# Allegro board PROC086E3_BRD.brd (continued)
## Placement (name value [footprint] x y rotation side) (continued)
R402  360E_1%  [RES0402_0-5]  30.05 111.19 90 bottom
R403  7.5K  [RES0402_0-5]  34.35 110.57 180 bottom
R404  47K_1%  [RES0402_0-5]  14.22 109.3 270 bottom
R405  10K  [RES0402_0-5#2]  31.6 106.4 180 bottom
R406  47K_1%  [RES0402_0-5]  14.22 106.2 90 bottom
R407  10K  [RES0402_0-5#2]  31.6 105.23 0 bottom
R408  1.5K_1%  [RES0402_0-5#2]  31.11 103.59 90 bottom
R409  7.5K  [RES0402_0-5]  35.11 103.23 180 bottom
R410  3.74K_1%  [RES0402_0-5#2]  33.45 102.61 90 bottom
R411  360E_1%  [RES0402_0-5]  29.48 102.98 0 bottom
R412  47.5E_1%  [RES0402_0-5#2]  16.36 102.43 180 bottom
R413  360E_1%  [RES0402_0-5]  26.98 102.61 270 bottom
R414  4.75K_1%  [RES0402_0-5#2]  25.75 102.61 90 bottom
R415  7.5K  [RES0402_0-5]  35.11 102 180 bottom
R416  47E  [RES0402_0-5]  33.26 100.61 0 bottom
R417  1.5K  [RES0402_0-5#2]  34.96 99.95 90 bottom
R418  49.9E_1%  [RES0402_0-5#2]  21.48 96.41 0 bottom
R419  0E  [RES0402_0-5#2]  26.16 95.92 270 bottom
R420  0E  [RES0402_0-5#2]  25.09 95.92 270 bottom
R421  100K  [RES0402_0-5]  24 95.92 90 bottom
R422  1.5K  [RES0402_0-5#2]  37.65 95.68 90 bottom
R423  3K  [RES0402_0-5#2]  31.05 95.43 0 bottom
R424  150K_1%  [RES0402_0-5#2]  21.48 95.26 180 bottom
R425  5.9K_1%  [RES0402_0-5#2]  16.46 91.85 270 bottom
R426  1.5K  [RES0402_0-5#2]  35.68 91.53 270 bottom
R427  0E  [RES0402_0-5#2]  14.8 91.36 0 bottom
R428  47E  [RES0402_0-5]  33.91 90.93 0 bottom
R429  47E  [RES0402_0-5]  33.26 89.96 0 bottom
R430  0E  [RES0402_0-5#2]  14.8 89.38 0 bottom
R431  1.5K  [RES0402_0-5#2]  34.96 89.4 90 bottom
R432  5.9K_1%  [RES0402_0-5#2]  16.46 88.89 90 bottom
R433  150K_1%  [RES0402_0-5#2]  22.13 86.79 180 bottom
R434  0E  [RES0402_0-5#2]  60.13 89.34 270 bottom
R435  3K  [RES0402_0-5#2]  31.05 85.58 0 bottom
R436  0E  [RES0402_0-5#2]  26.16 85.09 90 bottom
R437  0E  [RES0402_0-5#2]  25.09 85.09 90 bottom
R438  100K  [RES0402_0-5]  24 85.09 270 bottom
R439  1.5K  [RES0402_0-5#2]  37.65 85.08 90 bottom
R440  49.9E_1%  [RES0402_0-5#2]  22.13 84.6 0 bottom
R441  1.5K  [RES0402_0-5#2]  18.82 70.63 270 bottom
R442  47E  [RES0402_0-5]  17.11 70 0 bottom
R443  1.5K  [RES0402_0-5#2]  35.68 80.83 270 bottom
R444  47E  [RES0402_0-5]  33.91 80.22 0 bottom
R445  1.5K  [RES0402_0-5#2]  20.82 74.95 90 bottom
R446  0E  [RES0402_0-5#2]  60.13 77.55 90 bottom
R447  47E  [RES0402_0-5]  16.46 79.9 0 bottom
R448  1.5K  [RES0402_0-5#2]  18.17 79.33 90 bottom
R449  3K  [RES0402_0-5#2]  14.12 75.55 0 bottom
R450  1.5K  [RES0402_0-5#2]  17.17 70 0 top
R451  47E  [RES0402_0-5]  18.88 70.63 270 top
R452  1.5K  [RES0402_0-5#2]  20.82 74.95 90 top
R453  47E  [RES0402_0-5]  33.26 67.53 0 bottom
R454  1.5K  [RES0402_0-5#2]  34.96 66.92 90 bottom
R455  47E  [RES0402_0-5]  19.43 79.33 90 top
R456  1.5K  [RES0402_0-5#2]  17.72 79.9 0 top
R457  3K  [RES0402_0-5#2]  16.03 79.41 90 top
R458  49.9E_1%  [RES0402_0-5#2]  21.48 63.22 0 bottom
R459  1.5K  [RES0402_0-5#2]  37.65 62.74 90 bottom
R460  0E  [RES0402_0-5#2]  26.26 62.73 270 bottom
R461  0E  [RES0402_0-5#2]  25.09 62.73 270 bottom
R462  100K  [RES0402_0-5]  24.05 62.73 90 bottom
R463  3K  [RES0402_0-5#2]  31.05 62.24 0 bottom
R464  150K_1%  [RES0402_0-5#2]  21.48 62.15 180 bottom
R465  5.9K_1%  [RES0402_0-5#2]  16.46 58.93 270 bottom
R466  1.5K  [RES0402_0-5#2]  35.68 58.52 270 bottom
R467  0E  [RES0402_0-5#2]  14.8 58.44 0 bottom
R468  47E  [RES0402_0-5]  33.91 57.95 0 bottom
R469  47E  [RES0402_0-5]  33.26 56.82 0 bottom
R470  0E  [RES0402_0-5#2]  14.8 56.46 0 bottom
R471  1.5K  [RES0402_0-5#2]  34.96 56.21 90 bottom
R472  5.9K_1%  [RES0402_0-5#2]  16.46 55.97 90 bottom
R473  0E  [RES0402_0-5#2]  82.06 54.28 0 bottom
R474  150K_1%  [RES0402_0-5#2]  22.13 53.7 180 bottom
R475  0E  [RES0402_0-5#2]  82.06 53.09 0 bottom
R476  3K  [RES0402_0-5#2]  31.05 52.39 0 bottom
R477  1.5K  [RES0402_0-5#2]  37.65 52.14 90 bottom
R478  0E  [RES0402_0-5#2]  26.26 51.9 90 bottom
R479  0E  [RES0402_0-5#2]  25.09 51.9 90 bottom
R480  100K  [RES0402_0-5]  24.05 51.9 270 bottom
R481  49.9E_1%  [RES0402_0-5#2]  22.13 51.41 0 bottom
R482  10K  [RES0402_0-5#2]  22.32 49.23 180 bottom
R483  360E_1%  [RES0402_0-5]  23.98 43.07 0 bottom
R484  5.6K_1%  [RES0402_0-5#2]  23.98 41.84 180 bottom
R485  10K  [RES0402_0-5#2]  96.08 48.27 0 bottom
R486  1K_1%  [RES0402_0-5#2]  82.25 48.24 180 bottom
R487  10K  [RES0402_0-5#2]  22.32 48.06 0 bottom
R488  47.5E_1%  [RES0402_0-5#2]  16.36 47.96 180 bottom
R489  1.5K  [RES0402_0-5#2]  35.68 47.92 270 bottom
R490  47E  [RES0402_0-5]  33.91 47.32 0 bottom
R491  10K  [RES0402_0-5#2]  96.08 47.13 0 bottom
R492  1.5K_1%  [RES0402_0-5#2]  22.32 46.89 180 bottom
R493  7.5K  [RES0402_0-5]  27.29 45.87 180 bottom
R494  1.5K_1%  [RES0402_0-5#2]  25.64 45.25 90 bottom
R495  360E_1%  [RES0402_0-5]  23 45.25 90 bottom
R496  7.5K  [RES0402_0-5]  27.3 44.63 180 bottom
R497  47K_1%  [RES0402_0-5]  14.22 44.18 270 bottom
R498  10K  [RES0402_0-5#2]  46.75 46.93 0 bottom
R499  10K  [RES0402_0-5#2]  22.38 40.77 180 bottom
R500  47K_1%  [RES0402_0-5]  14.22 41.09 90 bottom
R501  10K  [RES0402_0-5#2]  22.38 39.6 0 bottom
R502  1.5K_1%  [RES0402_0-5#2]  23.26 37.81 90 bottom
R503  7.5K  [RES0402_0-5]  27.3 37.44 180 bottom
R504  47.5E_1%  [RES0402_0-5#2]  16.36 37.32 180 bottom
R505  1.5K_1%  [RES0402_0-5#2]  25.64 36.83 90 bottom
R506  360E_1%  [RES0402_0-5]  21.4 37.19 0 bottom
R507  360E_1%  [RES0402_0-5]  19.93 36.83 270 bottom
R508  5.6K_1%  [RES0402_0-5#2]  18.7 36.83 90 bottom
R509  7.5K  [RES0402_0-5]  27.3 36.21 180 bottom
R510  10K  [RES0402_0-5#2]  22.32 32.89 180 bottom
R511  360E_1%  [RES0402_0-5]  23.98 26.75 0 bottom
R512  5.6K_1%  [RES0402_0-5#2]  23.98 25.52 180 bottom
R513  10K  [RES0402_0-5#2]  22.32 31.72 0 bottom
R514  47.5E_1%  [RES0402_0-5#2]  16.36 31.62 180 bottom
R515  1.5K_1%  [RES0402_0-5#2]  22.32 30.56 180 bottom
R516  7.5K  [RES0402_0-5]  27.29 29.53 180 bottom
R517  3.74K_1%  [RES0402_0-5#2]  25.64 28.92 270 bottom
R518  360E_1%  [RES0402_0-5]  23 28.92 90 bottom
R519  7.5K  [RES0402_0-5]  27.3 28.3 180 bottom
R520  47K_1%  [RES0402_0-5]  14.22 27.93 270 bottom
R521  10K  [RES0402_0-5#2]  23.76 24.26 180 bottom
R522  47K_1%  [RES0402_0-5]  14.22 24.68 90 bottom
R523  10K  [RES0402_0-5#2]  23.76 23.09 0 bottom
R524  1.5K_1%  [RES0402_0-5#2]  23.27 21.47 90 bottom
R525  7.5K  [RES0402_0-5]  27.3 21.11 180 bottom
R526  47.5E_1%  [RES0402_0-5#2]  16.36 20.98 180 bottom
R527  3.74K_1%  [RES0402_0-5#2]  25.64 20.49 90 bottom
R528  360E_1%  [RES0402_0-5]  21.59 20.89 0 bottom
R529  360E_1%  [RES0402_0-5]  19.93 20.49 270 bottom
R530  5.6K_1%  [RES0402_0-5#2]  18.7 20.49 90 bottom
R531  7.5K  [RES0402_0-5]  27.3 19.88 180 bottom
R532  22E_1%  [RES0402_0-5]  65.53 164.4 90 top
R533  22E_1%  [RES0402_0-5]  66.75 164.4 90 top
R534  0E  [RES0402_0-5]  28.99 186.77 180 bottom
R535  0E  [RES0402_0-5]  28.99 185.58 180 bottom
R536  0E  [RES0603_0-75]  88.95 117.94 180 bottom
R537  0E  [RES0603_0-75]  90.43 117.94 0 bottom
R538  0E  [RES0402_0-5]  66.79 70.46 180 bottom
R539  0E  [RES0402_0-5]  65.95 70.46 0 bottom
SW1  EG-1218  [SW3_98-42_460X160_TH]  29.08 139.39 90 bottom
TP1  -  [TP40_SMD]  68.76 113.83 270 bottom
TP2  -  [TP40_SMD]  68.4 111.35 0 bottom
TP3  -  [TP40_SMD]  68.4 105.78 0 bottom
TP4  5002  [TP_CIR67D40_TH_4-6]  35.51 173.85 90 bottom
TP5  THRU HOLE  [TP_40X65]  73 94.67 180 bottom
TP6  THRU HOLE  [TP_40X65]  98.22 94.53 180 bottom
TP7  THRU HOLE  [TP_40X65]  95.2 81.47 180 bottom
TP8  THRU HOLE  [TP_40X65]  94.77 75.16 180 bottom
TP9  -  [TP40_SMD]  65.92 68.29 90 bottom
TP10  -  [TP40_SMD]  95.14 52.13 0 top
TP11  -  [TP40_SMD]  95.27 49.88 0 top
TP12  THRU HOLE  [TP_40X65]  99.14 47.33 180 bottom
TP13  -  [TP40_SMD]  41.19 46.43 0 top
TP14  -  [TP40_SMD]  41.19 43.13 0 top
TP15  -  [TP40_SMD]  45.75 193.92 180 bottom
TP16  -  [TP40_SMD]  45.75 191.8 180 bottom
TP17  -  [TP40_SMD]  24.36 187.89 270 bottom
TP18  -  [TP40_SMD]  66.07 186.29 180 bottom
TP19  -  [TP40_SMD]  20.15 186.77 90 bottom
TP21  -  [TP40_SMD]  20.23 180.87 90 bottom
TP22  -  [TP40_SMD]  28.93 179.73 90 bottom
TP23  -  [TP40_SMD]  20.23 178.73 90 bottom
TP24  -  [TP40_SMD]  65.56 178.47 180 bottom
TP25  -  [TP40_SMD]  99.99 174.75 90 bottom
TP26  -  [TP40_SMD]  67.57 176.94 180 bottom
TP27  -  [TP40_SMD]  18.1 175.98 90 bottom
TP28  -  [TP40_SMD]  25.76 175.88 90 bottom
TP29  -  [TP40_SMD]  23.58 175.88 90 bottom
TP30  -  [TP40_SMD]  27.41 174.38 90 bottom
TP31  -  [TP40_SMD]  26.69 162.7 90 bottom
TP32  -  [TP40_SMD]  56.77 152.91 270 bottom
TP33  -  [TP40_SMD]  65.75 160.11 0 bottom
TP34  -  [TP40_SMD]  63.79 160.11 0 bottom
TP35  -  [TP20_SMD]  80.06 158.96 180 bottom
TP36  -  [TP20_SMD]  82.42 159.06 180 bottom
TP37  -  [TP20_SMD]  77.32 158.76 180 bottom
TP38  -  [TP40_SMD]  71.39 156.29 0 bottom
TP39  -  [TP40_SMD]  73.47 155.41 0 bottom
TP40  -  [TP20_SMD]  89.54 155.15 0 bottom
TP41  -  [TP40_SMD]  54.94 134.56 270 bottom
TP42  -  [TP40_SMD]  48.26 149.33 0 bottom
TP43  -  [TP40_SMD]  46.1 149.33 0 bottom
TP44  -  [TP40_SMD]  81.89 145.09 90 bottom
TP45  -  [TP40_SMD]  77.99 144.73 90 bottom
TP46  -  [TP40_SMD]  72.85 145.3 90 bottom
TP47  -  [TP40_SMD]  39.12 140.95 0 bottom
TP48  -  [TP40_SMD]  48.46 136.51 0 bottom
TP49  -  [TP40_SMD]  46.33 136.51 0 bottom
TP50  -  [TP40_SMD]  44.42 136.51 0 bottom
TP51  -  [TP40_SMD]  91.3 128.51 180 bottom
TP52  -  [TP40_SMD]  93.85 128.38 180 bottom
TP53  -  [TP40_SMD]  93.85 126.47 180 bottom
TP54  -  [TP40_SMD]  60.66 126.14 270 bottom
TP55  -  [TP40_SMD]  81.89 124.82 180 bottom
TP56  -  [TP40_SMD]  79.83 124.82 180 bottom
TP57  5002  [TP_CIR67D40_TH_4-6]  22.6 80.03 270 bottom
TP58  -  [TP20_SMD]  51.61 62.24 180 bottom
TP59  -  [TP20_SMD]  51.61 63.25 180 bottom
TP60  -  [TP20_SMD]  41.35 59.91 180 bottom
TP61  -  [TP20_SMD]  41.35 60.91 180 bottom
TP62  -  [TP20_SMD]  33.28 23.5 180 bottom
TP63  -  [TP20_SMD]  34.28 23.5 180 bottom
TP64  -  [TP20_SMD]  42.01 29.42 180 bottom
TP65  -  [TP20_SMD]  42.01 28.42 180 bottom
TP66  -  [TP20_SMD]  42.47 34.8 180 bottom
TP67  -  [TP20_SMD]  42.47 35.8 180 bottom
TP68  -  [TP20_SMD]  37.08 45.75 180 bottom
TP69  -  [TP20_SMD]  37.08 44.75 180 bottom
TP70  -  [TP20_SMD]  45.47 96.43 180 bottom
TP71  -  [TP20_SMD]  45.47 97.44 180 bottom
TP72  -  [TP20_SMD]  39.12 88.81 180 bottom
TP73  -  [TP20_SMD]  40.12 88.81 180 bottom
TP74  -  [TP20_SMD]  40.55 74.79 180 bottom
TP75  -  [TP20_SMD]  24.68 76.83 180 bottom
TP76  -  [TP20_SMD]  23.68 76.83 180 bottom
TP77  -  [TP20_SMD]  41.55 74.79 180 bottom
TP78  -  [TP20_SMD]  38.61 107.44 180 bottom
TP79  -  [TP20_SMD]  39.61 107.44 180 bottom
TP80  -  [TP20_SMD]  39.02 115.03 180 bottom
TP81  -  [TP20_SMD]  40.02 115.03 180 bottom
TP82  -  [TP20_SMD]  34.09 119.93 180 bottom
TP83  -  [TP20_SMD]  34.09 120.93 180 bottom
TP84  -  [TP20_SMD]  33.67 123.35 180 bottom
TP85  -  [TP20_SMD]  32.67 123.35 180 bottom
TP86  -  [TP20_SMD]  82.96 117.64 180 bottom
TP87  -  [TP20_SMD]  84.02 116.49 180 bottom
TP88  -  [TP20_SMD]  82.99 116.49 180 bottom
TP89  -  [TP20_SMD]  84.03 114.51 180 bottom
TP90  -  [TP20_SMD]  83.82 117.64 180 bottom
TP91  -  [TP20_SMD]  81.98 108.01 180 bottom
TP92  -  [TP20_SMD]  83.02 108.01 180 bottom
TP93  -  [TP20_SMD]  60.44 106.39 180 bottom
TP94  -  [TP20_SMD]  81.97 109.33 180 bottom
TP95  -  [TP20_SMD]  92.41 117.01 180 bottom
TP96  -  [TP20_SMD]  93.44 116.01 180 bottom
TP97  -  [TP20_SMD]  92.41 118.51 180 bottom
TP98  -  [TP20_SMD]  93.44 118.51 180 bottom
TP99  -  [TP20_SMD]  93.44 117.01 180 bottom
TP100  -  [TP20_SMD]  93.44 119.51 180 bottom
TP101  -  [TP20_SMD]  92.48 124.54 180 bottom
TP102  -  [TP20_SMD]  61.28 133.67 180 bottom
TP103  -  [TP20_SMD]  60.91 27.9 180 bottom
TP104  -  [TP20_SMD]  80.33 53.51 180 bottom
TP105  -  [TP20_SMD]  19.02 176.87 180 bottom
TP106  -  [TP20_SMD]  59.28 133.67 180 bottom
TP107  -  [TP20_SMD]  23.08 185.48 180 bottom
TP108  -  [TP20_SMD]  30.77 186.77 180 bottom
TP109  -  [TP20_SMD]  27.58 185.48 180 bottom
TP110  -  [TP20_SMD]  47.9 131.68 180 bottom
TP111  -  [TP20_SMD]  46.58 131.73 180 bottom
TP112  -  [TP20_SMD]  40.89 145.97 180 bottom
TP113  -  [TP20_SMD]  40.84 147.11 180 bottom
TP114  -  [TP20_SMD]  59.28 128.1 180 bottom
TP115  -  [TP20_SMD]  59.28 127.08 180 bottom
TP116  -  [TP20_SMD]  71.34 122.45 180 bottom
TP117  -  [TP20_SMD]  67.26 160.57 180 bottom
TP118  -  [TP20_SMD]  75.44 171.86 180 bottom
TP119  -  [TP20_SMD]  75.44 170.99 180 bottom
TP120  -  [TP20_SMD]  60.6 159.67 180 bottom
TP121  -  [TP20_SMD]  70.74 157.46 180 bottom
TP122  -  [TP20_SMD]  60.66 158.81 180 bottom
TP123  -  [TP20_SMD]  80.82 49.13 180 bottom
TP124  -  [TP20_SMD]  65.89 144.08 180 bottom
TP125  -  [TP20_SMD]  86.22 141.79 180 bottom
TP126  -  [TP20_SMD]  56.08 155.46 180 bottom
TP127  -  [TP20_SMD]  83.72 76.37 180 bottom
TP128  -  [TP20_SMD]  83.72 77.39 180 bottom
TP129  -  [TP20_SMD]  63.88 129.84 180 bottom
TP130  -  [TP20_SMD]  62.81 130.13 180 bottom
TP131  -  [TP20_SMD]  44.1 166.89 180 bottom
TP132  -  [TP20_SMD]  38.49 166.89 180 bottom
TP133  -  [TP20_SMD]  83.77 127.51 180 bottom
TP134  -  [TP20_SMD]  83.72 128.43 180 bottom
TP135  -  [TP20_SMD]  73.53 156.83 180 bottom
TP136  -  [TP20_SMD]  29.01 169.17 180 bottom
TP137  -  [TP20_SMD]  92.41 100.51 180 bottom
TP138  -  [TP20_SMD]  92.47 113.36 180 bottom
TP139  -  [TP20_SMD]  53.37 153.75 180 bottom
TP140  -  [TP20_SMD]  50.95 154.85 180 bottom
TP141  -  [TP20_SMD]  51.94 154.85 180 bottom
TP142  -  [TP20_SMD]  31.44 165.75 180 bottom
TP143  -  [TP20_SMD]  97.49 64.32 180 bottom
TP144  -  [TP20_SMD]  96.47 64.32 180 bottom
TP145  -  [TP20_SMD]  83 59.13 180 bottom
TP146  -  [TP20_SMD]  83 65.63 180 bottom
TP147  -  [TP20_SMD]  84.03 59.13 180 bottom
TP148  -  [TP20_SMD]  65.33 146.24 180 bottom
TP149  -  [TP20_SMD]  67.87 146.24 180 bottom
TP150  -  [TP20_SMD]  66.57 146.24 180 bottom
TP151  -  [TP20_SMD]  94.51 39.61 180 bottom
TP152  -  [TP20_SMD]  92.46 122.56 180 bottom
TP153  -  [TP20_SMD]  93.44 120.51 180 bottom
TP154  -  [TP20_SMD]  93.44 121.51 180 bottom
TP155  -  [TP20_SMD]  74.32 119.79 180 bottom
TP156  -  [TP20_SMD]  81.99 130.79 180 bottom
TP157  -  [TP20_SMD]  92.41 109.01 180 bottom
TP158  -  [TP20_SMD]  83 97.01 180 bottom
TP159  -  [TP20_SMD]  84.03 98.01 180 bottom
TP160  -  [TP20_SMD]  84.03 97.01 180 bottom
TP161  -  [TP40_SMD]  44.9 40.33 180 bottom
TP162  -  [TP40_SMD]  56.35 51.71 180 bottom
TP164  -  [TP40_SMD]  60.02 110.39 180 bottom
TP165  -  [TP40_SMD]  59.53 103.92 180 bottom
TP167  -  [TP40_SMD]  34.11 184.12 180 bottom
TP168  -  [TP40_SMD]  26.8 188.9 180 bottom
TP169  -  [TP40_SMD]  59.84 47.43 180 bottom
TP170  -  [TP40_SMD]  62.18 110.35 180 bottom
TP171  -  [TP40_SMD]  41.18 39.69 270 bottom
TP172  -  [TP40_SMD]  58.4 89.24 90 bottom
U1  TLV7103318DSET  [WSON6_19-68_60X60]  62.2 194.45 180 top
U2  DS90UB926QSQE  [WQFN60_19-68_360X360_0-8]  24.58 180.23 90 top
U3  SN74AVC4T245DGVR  [TVSOP16_15-74_150X180]  39.09 170.92 270 top
U4  SN74AVC4T245DGVR  [TVSOP16_15-74_150X180]  43.9 170.92 270 top
U5  SN74AVC4T245DGVR  [TVSOP16_15-74_150X180]  48.72 170.92 270 top
U6  SN74AVCB164245VR  [TVSOP48_15-74_390X180_1-2]  56.74 170.92 90 top
U7  SN74AVCB164245VR  [TVSOP48_15-74_390X180_1-2]  68.05 170.92 90 top
U8  DS90UB921TRHSTQ1  [QFN48_19-68_280X280_0-8_EP5-2]  30.19 161.45 270 top
U9  PCA9306DCT  [SSOP8_25-59_120X110]  44.49 157.79 90 top
U10  SN74CBT16214CDGGR  [TSSOP56_19-68_560X240_1-2]  61.96 144.43 90 top
U11  SN74CBT16214CDGGR  [TSSOP56_19-68_560X240_1-2]  77.53 144.41 90 top
U12  SN74CBT16214CDGGR  [TSSOP56_19-68_560X240_1-2]  92.97 144.41 90 top
U13  SN74LVC2G14  [SC70-6]  26.2 138.29 90 top
U14  SN74AVC8T245PWR  [TSSOP24_25-59_315X180_1-2]  51.74 130.98 90 top
U15  TCA6416ARTWR  [WQFN24_19-68_160X160]  60.03 130.88 270 top
U16  OPA2322AIDGKR  [VSSOP8_25-59_120X120_1-1]  19.32 124.24 90 top
U17  SN74CB3Q3257PWR  [TSSOP16_25-59_205X180]  67.79 118.53 270 top
U18  OPA2322AIDGKR  [VSSOP8_25-59_120X120_1-1]  26.37 108.5 90 top
U19  PCM3168APAP  [HTQFP64_19-68_400X400_1-2_EP7-3X7]  52.34 107.14 180 top
U20  OPA2322AIDGKR  [VSSOP8_25-59_120X120_1-1]  33.91 95.67 90 top
U21  SN74LVC2G125DCUR  [VSSOP8_19-68_85X95]  65.16 94.35 270 bottom
U22  OPA2322AIDGKR  [VSSOP8_25-59_120X120_1-1]  22.13 90.37 90 top
U23  OPA2322AIDGKR  [VSSOP8_25-59_120X120_1-1]  33.91 85.06 90 top
U24  OPA2322AIDGKR  [VSSOP8_25-59_120X120_1-1]  28.98 72.55 270 top
U25  SN74LVC2G125DCUR  [VSSOP8_19-68_85X95]  63.58 69.84 270 bottom
U26  OPA2322AIDGKR  [VSSOP8_25-59_120X120_1-1]  28.98 72.55 270 bottom
U27  OPA2322AIDGKR  [VSSOP8_25-59_120X120_1-1]  33.91 62.74 90 top
U28  OPA2322AIDGKR  [VSSOP8_25-59_120X120_1-1]  22.13 57.45 90 top
U29  OPA2322AIDGKR  [VSSOP8_25-59_120X120_1-1]  33.91 52.14 90 top
U30  CAT24C256WI-GT3  [SOIC8_1-8]  74.35 51.01 180 top
U31  OPA2322AIDGKR  [VSSOP8_25-59_120X120_1-1]  19.32 42.56 90 top
U32  PCM3168APAP  [HTQFP64_19-68_400X400_1-2_EP7-3X7]  52.34 44.68 0 top
U33  OPA2322AIDGKR  [VSSOP8_25-59_120X120_1-1]  19.32 26.23 90 top
U34  TPD12S016PWR  [TSSOP24_25-59_315X180_1-2]  93.78 183.09 90 bottom
U35  SN74LVC2G125DCUR  [VSSOP8_19-68_85X95]  37 182.99 90 bottom
U36  PCA9306DCT  [SSOP8_25-59_120X110]  46.8 182.58 270 bottom
U37  PCA9306DCT  [SSOP8_25-59_120X110]  79.26 180.2 90 bottom
U38  24.000MHz  [OSC4_ASDMB_100X85_SMD_0-9]  38.52 179 180 bottom
U39  SN74LVC1G04DCKR  [SC70-5]  62.28 170.95 0 bottom
U40  TPS1H100AQPWPRQ1  [HTSSOP14_TPS1H100-Q1_180X200_1-2]  17.92 170.23 0 bottom
U41  TFP410PAP  [HTQFP64_19-68_400X400_1-2]  89.79 163.12 0 bottom
U42  CDCE813-Q1  [TSSOP14_25-59_205X180_1-2]  39.82 157.29 270 bottom
U43  TCA6416ARTWR  [WQFN24_19-68_160X160]  67 156.16 0 bottom
U44  TPS1H100AQPWPRQ1  [HTSSOP14_TPS1H100-Q1_180X200_1-2]  17.45 151.33 0 bottom
U45  DIR9001PW  [TSSOP28_25-59_390X180_1-2]  47.32 142.87 180 bottom
U46  OPA2322AIDGKR  [VSSOP8_25-59_120X120_1-1]  19.32 124.24 270 bottom
U47  OPA2322AIDGKR  [VSSOP8_25-59_120X120_1-1]  26.37 108.5 270 bottom
U48  OPA2322AIDGKR  [VSSOP8_25-59_120X120_1-1]  33.91 95.68 270 bottom
U49  OPA2322AIDGKR  [VSSOP8_25-59_120X120_1-1]  22.13 90.37 270 bottom
U50  OPA2322AIDGKR  [VSSOP8_25-59_120X120_1-1]  33.91 85.08 270 bottom
U51  OPA2322AIDGKR  [VSSOP8_25-59_120X120_1-1]  17.11 74.95 270 bottom
U52  OPA2322AIDGKR  [VSSOP8_25-59_120X120_1-1]  17.11 74.95 270 top
U53  OPA2322AIDGKR  [VSSOP8_25-59_120X120_1-1]  33.91 62.76 270 bottom
U54  OPA2322AIDGKR  [VSSOP8_25-59_120X120_1-1]  22.13 57.45 270 bottom
U55  OPA2322AIDGKR  [VSSOP8_25-59_120X120_1-1]  33.91 52.15 270 bottom
U56  OPA2322AIDGKR  [VSSOP8_25-59_120X120_1-1]  19.32 42.56 270 bottom
U57  OPA2322AIDGKR  [VSSOP8_25-59_120X120_1-1]  19.32 26.23 270 bottom
U179  OPA2322AIDGKR  [VSSOP8_25-59_120X120_1-1]  40.47 44.28 270 bottom
U180  OPA2322AIDGKR  [VSSOP8_25-59_120X120_1-1]  57.66 93.6 270 bottom
Y1  24.576MHz  [XTAL_CSM-7X_450X190_SMD_4-3]  58.98 143 90 bottom

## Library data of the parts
C1-C49 C51 C53-C63 C65-C71 C73-C88 C90-C121 C123-C133 C135-C167 C169-C182 C184-C195 C197-C203 C205-C278 C280-C285 C287-C292 C294-C300 C302-C331 C333-C337 C339-C358 C360-C365 C367-C372 C374-C379 C381-C385 C765-C774 = CAP
C50 C52 C64 C72 C89 C122 C134 C168 C183 C196 C204 C279 C286 C293 C301 C332 C338 C359 C366 C373 C380 = CAP_POL
D1-D4 = DIODE_TVS
FL1 FL2 FL4 FL6-FL15 FL20-FL25 = EMIFILTER_IND
FL3 FL5 FL16-FL19 = EMIFILTER_ACM
J1 J2 = CON_INT_60X2_M
J3 = RECP_16X2
J4 = CON_HDMI_19X1_TI
J5 J7 = CON_JACK4_EXG.0B.304
J6 = CON_FLEX_36X1_52559-3652
J8 J9 = CON_RCAJACK3_RCJ-02X
J10 = HEADER_8X1
J11-J13 J15 J16 J18 J19 = CON_AUDIOJACK6_STX-4235-3/3
J14 J20 = CON_PMC_20X2_F
J17 = CON_PMC_60X2_F_QSH-060
L1 = INDUCTOR
LD1-LD3 = LED_598-8170-107F
MOD1 = MODULE_PLR135T10
Q1-Q3 = MOSFET_2N7002_SOT23
R1-R8 R10 R11 R13-R25 R27-R30 R32 R47-R56 R58 R59 R62-R66 R68-R71 R96-R153 R155 R156 R158-R160 R162-R232 R234 R236-R269 R271-R273 R275 R277-R311 R313-R323 R325-R531 R534-R539 = RESISTOR
R26 R57 R60 R61 R67 R72-R95 R233 R235 = RESISTOR: signal model: RESISTOR_RES0402_0-5_0E_0E
R31 R33-R46 R154 R157 R161 R270 R274 R276 R312 R324 R532 R533 = RESISTOR: signal model: RESISTOR_RES0402_22E_1%_22E_1%
SW1 = SW3_SLIDE_EG1218
TP1-TP19 TP21-TP162 TP164 TP165 TP167-TP172 = TESTPOINT
U1 = TLV7103318D_WSON6
U2 = DS90UB926QSQ_WQFN60_TI
U3-U5 = SN74AVC4T245DGVR_TVSOP16
U6 U7 = SN74AVCB164245VR_TVSOP48
U8 = DS90UB921TRHSTQ1_WQFN48_TI
U9 U36 U37 = PCA9306DCT_SSOP8
U10-U12 = SN74CBT16214CDGGR_TSSOP56_TI
U13 = SN74LVC2G14DCKR_SC-70
U14 = SN74AVC8T245PWR_TSSOP24
U15 U43 = TCA6416ARTWR_WQFN24
U16 U18 U20 U22-U24 U26-U29 U31 U33 U46-U57 U179 U180 = OPA2350UA_SOIC8
U17 = SN74CB3Q3257PWR_TSSOP16
U19 U32 = PCM3168APAP_HTQFP64_TI
U21 U25 U35 = SN74LVC2G125DCUT_VSSOP8
U30 = CAT24C256WI-GT3_SOIC8
U34 = TPD12S016PW_TSSOP24
U38 = OSC4_ASDMB
U39 = SN74LVC1G04DCKR_SC70-5
U40 U44 = TPS1H100A-Q1_HTSSOP14
U41 = TFP410PAP_HTQFP64_TI
U42 = CDCE813QPWRQ1_TSSOP14
U45 = DIR9001PW_TSSOP28_TI
Y1 = CRY

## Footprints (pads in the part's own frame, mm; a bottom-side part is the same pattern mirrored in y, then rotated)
CAP0402_0-5
  rect 0.559x0.635 smd: 1(-0.49,0) 2(0.49,0)
CAP0402_0-75
  rect 0.559x0.635 smd: 1(-0.49,0) 2(0.49,0)
CAP0603_1
  rect 0.94x1.016 smd: 1(-0.8,0) 2(0.8,0)
CAP0805_1-5
  rect 1.143x1.448 smd: 1(-0.9,0) 2(0.9,0)
CAP1206_2
  rect 0.991x1.702 smd: 1(-1.35,0) 2(1.35,0)
CAP1206_2#2
  rect 1.143x1.803 smd: 1(-1.5,0) 2(1.5,0)
CAP_196-85_280X100_TH_6-5
  rect 1.448x1.448 hole 0.762: 1(0,0)
  round 1.448 hole 0.762: 2(5,0)
CAP_393-7_510X180_TH_10-5
  rect 1.549x1.549 hole 0.864: 1(0,0)
  round 1.549 hole 0.864: 2(10,0)
CAPCT0805H_1
  rect 0.66x1.549 smd: 1(-1.15,0) 2(1.15,0)
CON_19X1_10029449-001RLF_S_R_S_6-3
  rect 0.33x1.956 smd: 1(4.75,4.928) 2(4.25,4.928) 3(3.75,4.928) 4(3.25,4.928) 5(2.75,4.928) 6(2.25,4.928) 7(1.75,4.928) 8(1.25,4.928) 9(0.75,4.928) 10(0.25,4.928) 11(-0.25,4.928) 12(-0.75,4.928) 13(-1.25,4.928) 14(-1.75,4.928) 15(-2.25,4.928) 16(-2.75,4.928) 17(-3.25,4.928) 18(-3.75,4.928) 19(-4.25,4.928)
  round 2.007 hole 1.321: 20(7.25,3.928) 21(-7.25,3.928) 22(7.85,-0.972) 23(-7.85,-0.972)
CON_AV6_STX-4235-3-3_S_R_T_26
  oval 1.854x3.886 hole 1.981x4.013 unplated: (-7,0) (-3,0)
  rect 2.21x2.21 hole 1.524: 1A(0,0)
  round 2.21 hole 1.524: 1B(-10,0) 2A(1.25,7.5) 2B(-10,5) 5A(-11.25,7.5) 5B(0,5)
CON_FLEX1X36_52559-36_S_S_S_5-3
  rect 0.61x1.499 smd: 1(-8.75,-1.4) 2(-8.25,1.4) 3(-7.75,-1.4) 4(-7.25,1.4) 5(-6.75,-1.4) 6(-6.25,1.4) 7(-5.75,-1.4) 8(-5.25,1.4) 9(-4.75,-1.4) 10(-4.25,1.4) 11(-3.75,-1.4) 12(-3.25,1.4) 13(-2.75,-1.4) 14(-2.25,1.4) 15(-1.75,-1.4) 16(-1.25,1.4) 17(-0.75,-1.4) 18(-0.25,1.4) 19(0.25,-1.4) 20(0.75,1.4) 21(1.25,-1.4) 22(1.75,1.4) 23(2.25,-1.4) 24(2.75,1.4) 25(3.25,-1.4) 26(3.75,1.4) 27(4.25,-1.4) 28(4.75,1.4) 29(5.25,-1.4) 30(5.75,1.4) 31(6.25,-1.4) 32(6.75,1.4) 33(7.25,-1.4) 34(7.75,1.4) 35(8.25,-1.4) 36(8.75,1.4)
  rect 0.787x1.499 smd: SH1(-9.75,-1.4) SH2(-9.75,1.4) SH3(9.75,-1.4) SH4(9.75,1.4)
CON_JACK4_D4S20G-400A5_P_R_T_10-6
  rect 1.702x1.702 hole 1.016: 1(0,0)
  round 1.702 hole 1.016: 2(0,-2) 3(2,-2) 4(2,0)
  round 2.362 hole 1.676: SH1(-3.5,3.5) SH2(-3.5,-5.5) SH3(5.5,-5.5) SH4(5.5,3.5)
CON_PMC2X20_QSE-020-01-D-A_S_S_S_3-4
  round 0.889 hole 1.016 unplated: (-10.065,2.67) (10.065,2.67)
  rect 0.406x2.261 smd: 1(-7.595,-2.86) 2(-7.595,2.87) 3(-6.795,-2.86) 4(-6.795,2.87) 5(-5.995,-2.86) 6(-5.995,2.87) 7(-5.195,-2.86) 8(-5.195,2.87) 9(-4.395,-2.86) 10(-4.395,2.87) 11(-3.595,-2.86) 12(-3.595,2.87) 13(-2.795,-2.86) 14(-2.795,2.87) 15(-1.995,-2.86) 16(-1.995,2.87) 17(-1.195,-2.86) 18(-1.195,2.87) 19(-0.395,-2.86) 20(-0.395,2.87) 21(0.405,-2.86) 22(0.405,2.87) 23(1.205,-2.86) 24(1.205,2.87) 25(2.005,-2.86) 26(2.005,2.87) 27(2.805,-2.86) 28(2.805,2.87) 29(3.605,-2.86) 30(3.605,2.87) 31(4.405,-2.86) 32(4.405,2.87) 33(5.205,-2.86) 34(5.205,2.87) 35(6.005,-2.86) 36(6.005,2.87) 37(6.805,-2.86) 38(6.805,2.87) 39(7.605,-2.86) 40(7.605,2.87)
  rect 2.794x0.432 smd: 41(-8.065,0) 44(8.065,0)
  rect 4.699x0.432 smd: 42(-3.175,0) 43(3.175,0)
CON_PMC2X60_QSE-060-01-D-A_S_S_S_3-4
  round 0.889 hole 1.016 unplated: (-30.065,2.67) (30.065,2.67)
  rect 0.406x2.261 smd: 1(-27.595,-2.86) 2(-27.595,2.87) 3(-26.795,-2.86) 4(-26.795,2.87) 5(-25.995,-2.86) 6(-25.995,2.87) 7(-25.195,-2.86) 8(-25.195,2.87) 9(-24.395,-2.86) 10(-24.395,2.87) 11(-23.595,-2.86) 12(-23.595,2.87) 13(-22.795,-2.86) 14(-22.795,2.87) 15(-21.995,-2.86) 16(-21.995,2.87) 17(-21.195,-2.86) 18(-21.195,2.87) 19(-20.395,-2.86) 20(-20.395,2.87) 21(-19.595,-2.86) 22(-19.595,2.87) 23(-18.795,-2.86) 24(-18.795,2.87) 25(-17.995,-2.86) 26(-17.995,2.87) 27(-17.195,-2.86) 28(-17.195,2.87) 29(-16.395,-2.86) 30(-16.395,2.87) 31(-15.595,-2.86) 32(-15.595,2.87) 33(-14.795,-2.86) 34(-14.795,2.87) 35(-13.995,-2.86) 36(-13.995,2.87) 37(-13.195,-2.86) 38(-13.195,2.87) 39(-12.395,-2.86) 40(-12.395,2.87) 41(-7.595,-2.86) 42(-7.595,2.87) 43(-6.795,-2.86) 44(-6.795,2.87) 45(-5.995,-2.86) 46(-5.995,2.87) 47(-5.195,-2.86) 48(-5.195,2.87) 49(-4.395,-2.86) 50(-4.395,2.87) 51(-3.595,-2.86) 52(-3.595,2.87) 53(-2.795,-2.86) 54(-2.795,2.87) 55(-1.995,-2.86) 56(-1.995,2.87) 57(-1.195,-2.86) 58(-1.195,2.87) 59(-0.395,-2.86) 60(-0.395,2.87) 61(0.405,-2.86) 62(0.405,2.87) 63(1.205,-2.86) 64(1.205,2.87) 65(2.005,-2.86) 66(2.005,2.87) 67(2.805,-2.86) 68(2.805,2.87) 69(3.605,-2.86) 70(3.605,2.87) 71(4.405,-2.86) 72(4.405,2.87) 73(5.205,-2.86) 74(5.205,2.87) 75(6.005,-2.86) 76(6.005,2.87) 77(6.805,-2.86) 78(6.805,2.87) 79(7.605,-2.86) 80(7.605,2.87) 81(12.405,-2.86) 82(12.405,2.87) 83(13.205,-2.86) 84(13.205,2.87) 85(14.005,-2.86) 86(14.005,2.87) 87(14.805,-2.86) 88(14.805,2.87) 89(15.605,-2.86) 90(15.605,2.87) 91(16.405,-2.86) 92(16.405,2.87) 93(17.205,-2.86) 94(17.205,2.87) 95(18.005,-2.86) 96(18.005,2.87) 97(18.805,-2.86) 98(18.805,2.87) 99(19.605,-2.86) 100(19.605,2.87) 101(20.405,-2.86) 102(20.405,2.87) 103(21.205,-2.86) 104(21.205,2.87) 105(22.005,-2.86) 106(22.005,2.87) 107(22.805,-2.86) 108(22.805,2.87) 109(23.605,-2.86) 110(23.605,2.87) 111(24.405,-2.86) 112(24.405,2.87) 113(25.205,-2.86) 114(25.205,2.87) 115(26.005,-2.86) 116(26.005,2.87) 117(26.805,-2.86) 118(26.805,2.87) 119(27.605,-2.86) 120(27.605,2.87)
  rect 2.794x0.432 smd: 121(-28.065,0) 124(-11.935,0) 125(-8.065,0) 128(8.065,0) 129(11.935,0) 132(28.065,0)
  rect 4.699x0.432 smd: 122(-23.175,0) 123(-16.825,0) 126(-3.175,0) 127(3.175,0) 130(16.825,0) 131(23.175,0)
CON_PMC2X60_QTH-60-1-D-A_P_S_S_4-4
  round 0.889 hole 1.016 unplated: (-19.24,2.03) (19.239,2.03)
  rect 0.305x1.448 smd: 1(-17.251,3.08) 2(-17.251,-3.086) 3(-16.751,3.08) 4(-16.751,-3.086) 5(-16.251,3.08) 6(-16.251,-3.086) 7(-15.751,3.08) 8(-15.751,-3.086) 9(-15.251,3.08) 10(-15.251,-3.086) 11(-14.751,3.08) 12(-14.751,-3.086) 13(-14.251,3.08) 14(-14.251,-3.086) 15(-13.751,3.08) 16(-13.751,-3.086) 17(-13.251,3.08) 18(-13.251,-3.086) 19(-12.751,3.08) 20(-12.751,-3.086) 21(-12.251,3.08) 22(-12.251,-3.086) 23(-11.751,3.08) 24(-11.751,-3.086) 25(-11.251,3.08) 26(-11.251,-3.086) 27(-10.751,3.08) 28(-10.751,-3.086) 29(-10.251,3.08) 30(-10.251,-3.086) 31(-9.751,3.08) 32(-9.751,-3.086) 33(-9.251,3.08) 34(-9.251,-3.086) 35(-8.751,3.08) 36(-8.751,-3.086) 37(-8.251,3.08) 38(-8.251,-3.086) 39(-7.751,3.08) 40(-7.751,-3.086) 41(-7.251,3.08) 42(-7.251,-3.086) 43(-6.751,3.08) 44(-6.751,-3.086) 45(-6.251,3.08) 46(-6.251,-3.086) 47(-5.751,3.08) 48(-5.751,-3.086) 49(-5.251,3.08) 50(-5.251,-3.086) 51(-4.751,3.08) 52(-4.751,-3.086) 53(-4.251,3.08) 54(-4.251,-3.086) 55(-3.751,3.08) 56(-3.751,-3.086) 57(-3.251,3.08) 58(-3.251,-3.086) 59(-2.751,3.08) 60(-2.751,-3.086) 61(2.751,3.08) 62(2.751,-3.086) 63(3.251,3.08) 64(3.251,-3.086) 65(3.751,3.08) 66(3.751,-3.086) 67(4.251,3.08) 68(4.251,-3.086) 69(4.751,3.08) 70(4.751,-3.086) 71(5.251,3.08) 72(5.251,-3.086) 73(5.751,3.08) 74(5.751,-3.086) 75(6.251,3.08) 76(6.251,-3.086) 77(6.751,3.08) 78(6.751,-3.086) 79(7.251,3.08) 80(7.251,-3.086) 81(7.751,3.08) 82(7.751,-3.086) 83(8.251,3.08) 84(8.251,-3.086) 85(8.751,3.08) 86(8.751,-3.086) 87(9.251,3.08) 88(9.251,-3.086) 89(9.751,3.08) 90(9.751,-3.086) 91(10.251,3.08) 92(10.251,-3.086) 93(10.751,3.08) 94(10.751,-3.086) 95(11.251,3.08) 96(11.251,-3.086) 97(11.751,3.08) 98(11.751,-3.086) 99(12.251,3.08) 100(12.251,-3.086) 101(12.751,3.08) 102(12.751,-3.086) 103(13.251,3.08) 104(13.251,-3.086) 105(13.751,3.08) 106(13.751,-3.086) 107(14.251,3.08) 108(14.251,-3.086) 109(14.751,3.08) 110(14.751,-3.086) 111(15.251,3.08) 112(15.251,-3.086) 113(15.751,3.08) 114(15.751,-3.086) 115(16.251,3.08) 116(16.251,-3.086) 117(16.751,3.08) 118(16.751,-3.086) 119(17.251,3.08) 120(17.251,-3.086)
  rect 2.54x0.635 smd: 121(-18.441,0) 124(-1.551,0) 125(1.561,0) 128(18.451,0)
  rect 4.699x0.635 smd: 122(-13.172,0) 123(-6.822,0) 126(6.832,0) 127(13.182,0)
CON_RCAJACK3_RCJ-02X_S_S_T_16
  rect 2.692x2.692 hole 1.981: 1(0,0)
  round 2.362 hole 1.676: 2(5.15,1.6)
  round 2.692 hole 1.981: 3(10.3,0)
DIO_SMC
  rect 2.21x3.099 smd: 1(-3.5,0) 2(3.5,0)
DIO_SOD923_0-5
  rect 0.432x0.33 smd: 1(-0.55,0) 2(0.55,0)
EMIFIL_BLM15A_0402_0-6
  rect 0.61x0.61 smd: 1(-0.46,0) 2(0.46,0)
FILT4_MCZ1210DH_60X50_SMD_0-6
  rect 0.508x0.305 smd: 1(-0.612,0.275) 2(-0.612,-0.275) 3(0.612,-0.275) 4(0.612,0.275)
HDR_1X8_77311-818-08_S_T_8-6
  rect 1.702x1.702 hole 1.016: 1(0,0)
  round 1.702 hole 1.016: 2(-2.54,0) 3(-5.08,0) 4(-7.62,0) 5(-10.16,0) 6(-12.7,0) 7(-15.24,0) 8(-17.78,0)
HTQFP64_19-68_400X400_1-2
  rect 1.499x0.305 smd: 1(-5.7,3.75) 2(-5.7,3.25) 3(-5.7,2.75) 4(-5.7,2.25) 5(-5.7,1.75) 6(-5.7,1.25) 7(-5.7,0.75) 8(-5.7,0.25) 9(-5.7,-0.25) 10(-5.7,-0.75) 11(-5.7,-1.25) 12(-5.7,-1.75) 13(-5.7,-2.25) 14(-5.7,-2.75) 15(-5.7,-3.25) 16(-5.7,-3.75) 33(5.7,-3.75) 34(5.7,-3.25) 35(5.7,-2.75) 36(5.7,-2.25) 37(5.7,-1.75) 38(5.7,-1.25) 39(5.7,-0.75) 40(5.7,-0.25) 41(5.7,0.25) 42(5.7,0.75) 43(5.7,1.25) 44(5.7,1.75) 45(5.7,2.25) 46(5.7,2.75) 47(5.7,3.25) 48(5.7,3.75)
  rect 0.305x1.499 smd: 17(-3.75,-5.7) 18(-3.25,-5.7) 19(-2.75,-5.7) 20(-2.25,-5.7) 21(-1.75,-5.7) 22(-1.25,-5.7) 23(-0.75,-5.7) 24(-0.25,-5.7) 25(0.25,-5.7) 26(0.75,-5.7) 27(1.25,-5.7) 28(1.75,-5.7) 29(2.25,-5.7) 30(2.75,-5.7) 31(3.25,-5.7) 32(3.75,-5.7) 49(3.75,5.7) 50(3.25,5.7) 51(2.75,5.7) 52(2.25,5.7) 53(1.75,5.7) 54(1.25,5.7) 55(0.75,5.7) 56(0.25,5.7) 57(-0.25,5.7) 58(-0.75,5.7) 59(-1.25,5.7) 60(-1.75,5.7) 61(-2.25,5.7) 62(-2.75,5.7) 63(-3.25,5.7) 64(-3.75,5.7)
  rect 8.001x8.001 smd: 65(0,0)
HTQFP64_19-68_400X400_1-2_EP7-3X7
  rect 1.499x0.305 smd: 1(-5.7,3.75) 2(-5.7,3.25) 3(-5.7,2.75) 4(-5.7,2.25) 5(-5.7,1.75) 6(-5.7,1.25) 7(-5.7,0.75) 8(-5.7,0.25) 9(-5.7,-0.25) 10(-5.7,-0.75) 11(-5.7,-1.25) 12(-5.7,-1.75) 13(-5.7,-2.25) 14(-5.7,-2.75) 15(-5.7,-3.25) 16(-5.7,-3.75) 33(5.7,-3.75) 34(5.7,-3.25) 35(5.7,-2.75) 36(5.7,-2.25) 37(5.7,-1.75) 38(5.7,-1.25) 39(5.7,-0.75) 40(5.7,-0.25) 41(5.7,0.25) 42(5.7,0.75) 43(5.7,1.25) 44(5.7,1.75) 45(5.7,2.25) 46(5.7,2.75) 47(5.7,3.25) 48(5.7,3.75)
  rect 0.305x1.499 smd: 17(-3.75,-5.7) 18(-3.25,-5.7) 19(-2.75,-5.7) 20(-2.25,-5.7) 21(-1.75,-5.7) 22(-1.25,-5.7) 23(-0.75,-5.7) 24(-0.25,-5.7) 25(0.25,-5.7) 26(0.75,-5.7) 27(1.25,-5.7) 28(1.75,-5.7) 29(2.25,-5.7) 30(2.75,-5.7) 31(3.25,-5.7) 32(3.75,-5.7) 49(3.75,5.7) 50(3.25,5.7) 51(2.75,5.7) 52(2.25,5.7) 53(1.75,5.7) 54(1.25,5.7) 55(0.75,5.7) 56(0.25,5.7) 57(-0.25,5.7) 58(-0.75,5.7) 59(-1.25,5.7) 60(-1.75,5.7) 61(-2.25,5.7) 62(-2.75,5.7) 63(-3.25,5.7) 64(-3.75,5.7)
  rect 7.29x7.01 smd: 65(0,0)
HTSSOP14_TPS1H100-Q1_180X200_1-2
  rect 1.6x0.305 smd: 1(-2.8,1.95) 2(-2.8,1.3) 3(-2.8,0.65) 4(-2.8,0) 5(-2.8,-0.65) 6(-2.8,-1.3) 7(-2.8,-1.95) 8(2.8,-1.95) 9(2.8,-1.3) 10(2.8,-0.65) 11(2.8,0) 12(2.8,0.65) 13(2.8,1.3) 14(2.8,1.95)
  rect 3.404x5.004 smd: 15(0,0)
INDP1210
  rect 1.803x2.007 smd: 1(-1.4,0) 2(1.4,0)
LED_0805
  rect 0.889x1.295 smd: 1(-0.8,0) 2(0.8,0)
LED_0805_0-7
  rect 0.914x1.397 smd: 1(-1,0) 2(1,0)
MOD5_PLR135T10
  rect 1.575x1.575 hole 0.864: 1(0,0)
  round 1.575 hole 0.864: 2(-2.54,0) 3(-5.08,0)
  round 1.88 hole 1.168: 4(0,2.63) 5(-5.08,2.63)
OSC4_ASDMB_100X85_SMD_0-9
  rect 0.66x0.864 smd: 1(-0.825,-0.775) 2(0.825,-0.775) 3(0.825,0.775) 4(-0.825,0.775)
QFN48_19-68_280X280_0-8_EP5-2
  rect 0.838x0.305 smd: 1(-3.5,2.75) 2(-3.5,2.25) 3(-3.5,1.75) 4(-3.5,1.25) 5(-3.5,0.75) 6(-3.5,0.25) 7(-3.5,-0.25) 8(-3.5,-0.75) 9(-3.5,-1.25) 10(-3.5,-1.75) 11(-3.5,-2.25) 12(-3.5,-2.75) 25(3.5,-2.75) 26(3.5,-2.25) 27(3.5,-1.75) 28(3.5,-1.25) 29(3.5,-0.75) 30(3.5,-0.25) 31(3.5,0.25) 32(3.5,0.75) 33(3.5,1.25) 34(3.5,1.75) 35(3.5,2.25) 36(3.5,2.75)
  rect 0.305x0.838 smd: 13(-2.75,-3.5) 14(-2.25,-3.5) 15(-1.75,-3.5) 16(-1.25,-3.5) 17(-0.75,-3.5) 18(-0.25,-3.5) 19(0.25,-3.5) 20(0.75,-3.5) 21(1.25,-3.5) 22(1.75,-3.5) 23(2.25,-3.5) 24(2.75,-3.5) 37(2.75,3.5) 38(2.25,3.5) 39(1.75,3.5) 40(1.25,3.5) 41(0.75,3.5) 42(0.25,3.5) 43(-0.25,3.5) 44(-0.75,3.5) 45(-1.25,3.5) 46(-1.75,3.5) 47(-2.25,3.5) 48(-2.75,3.5)
  rect 5.207x5.207 smd: 49(0,0)
RECPT_2X16_SSW-116-D-RA_R_T_5
  rect 1.702x1.702 hole 1.016: 1(0,0)
  round 1.702 hole 1.016: 2(0,2.54) 3(-2.54,0) 4(-2.54,2.54) 5(-5.08,0) 6(-5.08,2.54) 7(-7.62,0) 8(-7.62,2.54) 9(-10.16,0) 10(-10.16,2.54) 11(-12.7,0) 12(-12.7,2.54) 13(-15.24,0) 14(-15.24,2.54) 15(-17.78,0) 16(-17.78,2.54) 17(-20.32,0) 18(-20.32,2.54) 19(-22.86,0) 20(-22.86,2.54) 21(-25.4,0) 22(-25.4,2.54) 23(-27.94,0) 24(-27.94,2.54) 25(-30.48,0) 26(-30.48,2.54) 27(-33.02,0) 28(-33.02,2.54) 29(-35.56,0) 30(-35.56,2.54) 31(-38.1,0) 32(-38.1,2.54)
RES0402_0-5
  rect 0.483x0.508 smd: 1(-0.42,0) 2(0.42,0)
RES0402_0-5#2
  rect 0.559x0.635 smd: 1(-0.49,0) 2(0.49,0)
RES0402_0-75
  rect 0.559x0.635 smd: 1(-0.49,0) 2(0.49,0)
RES0603_0-75
  rect 0.635x0.991 smd: 1(-0.74,0) 2(0.74,0)
SC70-5
  rect 0.94x0.406 smd: 1(-1.1,0.65) 2(-1.1,0) 3(-1.1,-0.65) 4(1.1,-0.65) 5(1.1,0.65)
SC70-6
  rect 0.864x0.356 smd: 1(-1.1,0.65) 2(-1.1,0) 3(-1.1,-0.65) 4(1.1,-0.65) 5(1.1,0) 6(1.1,0.65)
SOIC8_1-8
  rect 2.007x0.61 smd: 1(-2.4,1.905) 2(-2.4,0.635) 3(-2.4,-0.635) 4(-2.4,-1.905) 5(2.4,-1.905) 6(2.4,-0.635) 7(2.4,0.635) 8(2.4,1.905)
SOT23-123_1-1
  rect 0.838x0.61 smd: 1(-1.05,0.95) 2(-1.05,-0.95) 3(1.05,0)
SSOP8_25-59_120X110
  rect 1.092x0.406 smd: 1(-1.9,0.975) 2(-1.9,0.325) 3(-1.9,-0.325) 4(-1.9,-0.975) 5(1.9,-0.975) 6(1.9,-0.325) 7(1.9,0.325) 8(1.9,0.975)
SW3_98-42_460X160_TH
  rect 1.702x1.702 hole 1.016: 1(0,0)
  round 1.702 hole 1.016: 2(2.5,0) 3(5,0)
TP20_SMD
  round 0.508 smd: 1(0,0)
TP40_SMD
  round 1.016 smd: 1(0,0)
TP_40X65
  round 1.651 hole 1.016: 1(0,0)
TP_CIR67D40_TH_4-6
  round 1.702 hole 1.016: 1(0,0)
TSSOP14_25-59_205X180_1-2
  rect 1.499x0.457 smd: 1(-2.9,1.95) 2(-2.9,1.3) 3(-2.9,0.65) 4(-2.9,0) 5(-2.9,-0.65) 6(-2.9,-1.3) 7(-2.9,-1.95) 8(2.9,-1.95) 9(2.9,-1.3) 10(2.9,-0.65) 11(2.9,0) 12(2.9,0.65) 13(2.9,1.3) 14(2.9,1.95)
TSSOP16_25-59_205X180
  rect 1.6x0.356 smd: 1(-2.8,2.275) 2(-2.8,1.625) 3(-2.8,0.975) 4(-2.8,0.325) 5(-2.8,-0.325) 6(-2.8,-0.975) 7(-2.8,-1.625) 8(-2.8,-2.275) 9(2.8,-2.275) 10(2.8,-1.625) 11(2.8,-0.975) 12(2.8,-0.325) 13(2.8,0.325) 14(2.8,0.975) 15(2.8,1.625) 16(2.8,2.275)
TSSOP24_25-59_315X180_1-2
  rect 1.448x0.457 smd: 1(-2.9,3.575) 2(-2.9,2.925) 3(-2.9,2.275) 4(-2.9,1.625) 5(-2.9,0.975) 6(-2.9,0.325) 7(-2.9,-0.325) 8(-2.9,-0.975) 9(-2.9,-1.625) 10(-2.9,-2.275) 11(-2.9,-2.925) 12(-2.9,-3.575) 13(2.9,-3.575) 14(2.9,-2.925) 15(2.9,-2.275) 16(2.9,-1.625) 17(2.9,-0.975) 18(2.9,-0.325) 19(2.9,0.325) 20(2.9,0.975) 21(2.9,1.625) 22(2.9,2.275) 23(2.9,2.925) 24(2.9,3.575)
TSSOP28_25-59_390X180_1-2
  rect 1.499x0.457 smd: 1(-2.9,4.225) 2(-2.9,3.575) 3(-2.9,2.925) 4(-2.9,2.275) 5(-2.9,1.625) 6(-2.9,0.975) 7(-2.9,0.325) 8(-2.9,-0.325) 9(-2.9,-0.975) 10(-2.9,-1.625) 11(-2.9,-2.275) 12(-2.9,-2.925) 13(-2.9,-3.575) 14(-2.9,-4.225) 15(2.9,-4.225) 16(2.9,-3.575) 17(2.9,-2.925) 18(2.9,-2.275) 19(2.9,-1.625) 20(2.9,-0.975) 21(2.9,-0.325) 22(2.9,0.325) 23(2.9,0.975) 24(2.9,1.625) 25(2.9,2.275) 26(2.9,2.925) 27(2.9,3.575) 28(2.9,4.225)
TSSOP56_19-68_560X240_1-2
  rect 1.499x0.305 smd: 1(-3.75,6.75) 2(-3.75,6.25) 3(-3.75,5.75) 4(-3.75,5.25) 5(-3.75,4.75) 6(-3.75,4.25) 7(-3.75,3.75) 8(-3.75,3.25) 9(-3.75,2.75) 10(-3.75,2.25) 11(-3.75,1.75) 12(-3.75,1.25) 13(-3.75,0.75) 14(-3.75,0.25) 15(-3.75,-0.25) 16(-3.75,-0.75) 17(-3.75,-1.25) 18(-3.75,-1.75) 19(-3.75,-2.25) 20(-3.75,-2.75) 21(-3.75,-3.25) 22(-3.75,-3.75) 23(-3.75,-4.25) 24(-3.75,-4.75) 25(-3.75,-5.25) 26(-3.75,-5.75) 27(-3.75,-6.25) 28(-3.75,-6.75) 29(3.75,-6.75) 30(3.75,-6.25) 31(3.75,-5.75) 32(3.75,-5.25) 33(3.75,-4.75) 34(3.75,-4.25) 35(3.75,-3.75) 36(3.75,-3.25) 37(3.75,-2.75) 38(3.75,-2.25) 39(3.75,-1.75) 40(3.75,-1.25) 41(3.75,-0.75) 42(3.75,-0.25) 43(3.75,0.25) 44(3.75,0.75) 45(3.75,1.25) 46(3.75,1.75) 47(3.75,2.25) 48(3.75,2.75) 49(3.75,3.25) 50(3.75,3.75) 51(3.75,4.25) 52(3.75,4.75) 53(3.75,5.25) 54(3.75,5.75) 55(3.75,6.25) 56(3.75,6.75)
TVSOP16_15-74_150X180
  rect 1.499x0.203 smd: 1(-2.9,1.4) 2(-2.9,1) 3(-2.9,0.6) 4(-2.9,0.2) 5(-2.9,-0.2) 6(-2.9,-0.6) 7(-2.9,-1) 8(-2.9,-1.4) 9(2.9,-1.4) 10(2.9,-1) 11(2.9,-0.6) 12(2.9,-0.2) 13(2.9,0.2) 14(2.9,0.6) 15(2.9,1) 16(2.9,1.4)
TVSOP48_15-74_390X180_1-2
  rect 1.499x0.203 smd: 1(-2.9,4.6) 2(-2.9,4.2) 3(-2.9,3.8) 4(-2.9,3.4) 5(-2.9,3) 6(-2.9,2.6) 7(-2.9,2.2) 8(-2.9,1.8) 9(-2.9,1.4) 10(-2.9,1) 11(-2.9,0.6) 12(-2.9,0.2) 13(-2.9,-0.2) 14(-2.9,-0.6) 15(-2.9,-1) 16(-2.9,-1.4) 17(-2.9,-1.8) 18(-2.9,-2.2) 19(-2.9,-2.6) 20(-2.9,-3) 21(-2.9,-3.4) 22(-2.9,-3.8) 23(-2.9,-4.2) 24(-2.9,-4.6) 25(2.9,-4.6) 26(2.9,-4.2) 27(2.9,-3.8) 28(2.9,-3.4) 29(2.9,-3) 30(2.9,-2.6) 31(2.9,-2.2) 32(2.9,-1.8) 33(2.9,-1.4) 34(2.9,-1) 35(2.9,-0.6) 36(2.9,-0.2) 37(2.9,0.2) 38(2.9,0.6) 39(2.9,1) 40(2.9,1.4) 41(2.9,1.8) 42(2.9,2.2) 43(2.9,2.6) 44(2.9,3) 45(2.9,3.4) 46(2.9,3.8) 47(2.9,4.2) 48(2.9,4.6)
unnamed#2
  round 2.616 hole 2.743 unplated: (0,0)
unnamed#3
  round 0.686 hole 0.813 unplated: (-1.27,1.254) (0,1.254) (1.27,1.254)
VSSOP8_19-68_85X95
  rect 0.813x0.305 smd: 1(-1.55,0.75) 2(-1.55,0.25) 3(-1.55,-0.25) 4(-1.55,-0.75) 5(1.55,-0.75) 6(1.55,-0.25) 7(1.55,0.25) 8(1.55,0.75)
VSSOP8_25-59_120X120_1-1
  rect 1.397x0.457 smd: 1(-2.2,0.975) 2(-2.2,0.325) 3(-2.2,-0.325) 4(-2.2,-0.975) 5(2.2,-0.975) 6(2.2,-0.325) 7(2.2,0.325) 8(2.2,0.975)
WQFN24_19-68_160X160
  rect 0.813x0.305 smd: 1(-2,1.25) 2(-2,0.75) 3(-2,0.25) 4(-2,-0.25) 5(-2,-0.75) 6(-2,-1.25) 13(2,-1.25) 14(2,-0.75) 15(2,-0.25) 16(2,0.25) 17(2,0.75) 18(2,1.25)
  rect 0.305x0.813 smd: 7(-1.25,-2) 8(-0.75,-2) 9(-0.25,-2) 10(0.25,-2) 11(0.75,-2) 12(1.25,-2) 19(1.25,2) 20(0.75,2) 21(0.25,2) 22(-0.25,2) 23(-0.75,2) 24(-1.25,2)
  rect 2.692x2.692 smd: 25(0,0)
WQFN60_19-68_360X360_0-8
  rect 1.041x0.305 smd: 1(-4.35,3.5) 2(-4.35,3) 3(-4.35,2.5) 4(-4.35,2) 5(-4.35,1.5) 6(-4.35,1) 7(-4.35,0.5) 8(-4.35,0) 9(-4.35,-0.5) 10(-4.35,-1) 11(-4.35,-1.5) 12(-4.35,-2) 13(-4.35,-2.5) 14(-4.35,-3) 15(-4.35,-3.5) 31(4.35,-3.5) 32(4.35,-3) 33(4.35,-2.5) 34(4.35,-2) 35(4.35,-1.5) 36(4.35,-1) 37(4.35,-0.5) 38(4.35,0) 39(4.35,0.5) 40(4.35,1) 41(4.35,1.5) 42(4.35,2) 43(4.35,2.5) 44(4.35,3) 45(4.35,3.5)
  rect 0.305x1.041 smd: 16(-3.5,-4.35) 17(-3,-4.35) 18(-2.5,-4.35) 19(-2,-4.35) 20(-1.5,-4.35) 21(-1,-4.35) 22(-0.5,-4.35) 23(0,-4.35) 24(0.5,-4.35) 25(1,-4.35) 26(1.5,-4.35) 27(2,-4.35) 28(2.5,-4.35) 29(3,-4.35) 30(3.5,-4.35) 46(3.5,4.35) 47(3,4.35) 48(2.5,4.35) 49(2,4.35) 50(1.5,4.35) 51(1,4.35) 52(0.5,4.35) 53(0,4.35) 54(-0.5,4.35) 55(-1,4.35) 56(-1.5,4.35) 57(-2,4.35) 58(-2.5,4.35) 59(-3,4.35) 60(-3.5,4.35)
  rect 6.401x6.401 smd: 61(0,0)
WSON6_19-68_60X60
  rect 0.965x0.305 smd: 1(-0.65,0.5) 2(-0.65,0) 3(-0.65,-0.5) 4(0.65,-0.5) 5(0.65,0) 6(0.65,0.5)
XTAL_CSM-7X_450X190_SMD_4-3
  rect 5.512x2.007 smd: 1(-4.75,0) 2(4.75,0)

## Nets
DGND: C1.2 C2.2 C3.2 C4.2 C5.2 C6.2 C7.2 C8.2 C9.2 C10.2 C11.2 C12.2 C13.2 C14.2 C15.2 C18.2 C19.2 C20.2 C21.2 C22.2 C23.2 C24.2 C25.2 C26.2 C27.2 C28.2 C29.2 C30.2 C31.2 C32.2 C33.2 C34.2 C35.2 C38.2 C39.2 C40.2 C41.2 C42.1 C43.2 C44.2 C45.2 C46.2 C48.2 C49.2 C50.2 C54.2 C58.2 C60.2 C61.2 C62.2 C63.2 C70.2 C74.2 C77.2 C78.2 C79.2 C80.2 C82.2 C83.2 C84.2 C85.2 C86.2 C87.2 C93.2 C94.2 C95.2 C97.2 C99.2 C100.2 C101.2 C102.2 C103.2 C107.2 C109.2 C110.2 C112.2 C113.2 C116.2 C119.2 C124.2 C126.2 C127.2 C128.2 C130.2 C131.2 C132.2 C133.2 C136.2 C137.2 C138.2 C139.2 C141.2 C144.2 C145.2 C149.2 C152.2 C155.2 C157.2 C159.2 C161.2 C162.2 C164.2 C165.2 C166.2 C167.2 C171.2 C174.2 C175.2 C176.2 C178.2 C179.2 C180.2 C181.2 C182.2 C188.2 C190.2 C191.2 C192.2 C193.2 C194.2 C195.2 C201.2 C203.2 C210.2 C211.2 C212.2 C213.2 C214.2 C215.2 C216.2 C217.2 C218.2 C219.2 C220.2 C221.2 C222.2 C223.2 C224.2 C225.2 C226.2 C227.2 C228.2 C229.2 C230.1 C231.2 C232.2 C233.2 C234.2 C235.2 C236.2 C237.2 C238.2 C239.2 C240.2 C241.2 C242.2 C243.2 C244.1 C245.1 C246.1 C247.2 C248.1 C249.2 C250.1 C251.2 C252.2 C253.2 C254.2 C255.2 C256.2 C257.2 C258.2 C259.1 C260.2 C261.2 C262.2 C263.2 C264.2 C265.2 C266.2 C267.2 C268.2 C269.2 C270.2 C271.2 C272.2 C273.2 C274.2 C275.2 C276.2 C277.2 C278.2 C285.2 C298.2 C299.2 C303.2 C309.2 C311.2 C312.2 C314.2 C317.2 C320.2 C324.2 C325.2 C328.2 C330.2 C334.2 C336.2 C341.2 C344.2 C346.2 C348.1 C349.2 C352.2 C356.2 C357.2 C365.2 C369.2 C379.2 C765.2 C766.2 C767.2 C768.2 C769.2 C770.2 C771.2 C772.2 C773.2 C774.2 D1.2(ANODE) D2.2(ANODE) D3.2(ANODE) D4.2(ANODE) FL13.1 J1.1 J1.3 J1.5 J1.19 J1.20 J1.37 J1.38 J1.51 J1.52 J1.67 J1.68 J1.81 J1.82 J1.95 J1.96 J1.107 J1.108 J1.119 J1.120 J1.121 J1.122 J1.123 J1.124 J1.125 J1.126 J1.127 J1.128 J2.1 J2.3 J2.5 J2.39 J2.40 J2.67 J2.68 J2.77 J2.79 J2.81 J2.105 J2.119 J2.120 J2.121 J2.122 J2.123 J2.124 J2.125 J2.126 J2.127 J2.128 J3.16 J3.18 J3.22 J3.31 J3.32 J4.2(GND#2) J4.5(GND#5) J4.8(GND#8) J4.11(GND#11) J5.1 J5.SH1 J5.SH2 J5.SH3 J5.SH4 J6.6 J6.8 J6.10 J6.25 J6.26 J6.SH1 J6.SH2 J6.SH3 J6.SH4 J7.4 J7.SH1 J7.SH2 J7.SH3 J7.SH4 J8.1 J8.3 J10.8 J11.1A J11.1B J12.1A J12.1B J13.1A J13.1B J14.2 J14.4 J14.10 J14.19 J14.20 J14.29 J14.30 J14.39 J14.40 J14.41(GND1) J14.42(GND2) J14.43(GND3) J14.44(GND4) J15.1A J15.1B J16.1A J16.1B J17.26 J17.27 J17.77 J17.78 J17.115 J17.116 J17.121 J17.122 J17.123 J17.124 J17.125 J17.126 J17.127 J17.128 J17.129 J17.130 J17.131 J17.132 J18.1A J18.1B J19.1A J19.1B J20.19 J20.20 J20.41(GND1) J20.42(GND2) J20.43(GND3) J20.44(GND4) MOD1.2(GND) Q1.2(SOURCE) Q2.2(SOURCE) Q3.2(SOURCE) R1.1 R4.1 R5.1 R10.1 R14.2 R16.2 R23.2 R24.2 R25.2 R28.2 R47.1 R48.2 R49.2 R52.2 R53.2 R55.1 R58.2 R59.2 R70.2 R71.2 R96.1 R97.1 R98.1 R99.2 R102.2 R108.2 R112.2 R116.1 R118.2 R120.1 R128.2 R129.2 R130.1 R142.2 R151.2 R155.2 R156.2 R158.1 R166.1 R174.1 R176.1 R183.2 R195.1 R213.2 R225.1 R243.1 R254.2 R263.1 R266.2 R269.2 R272.1 R273.2 R278.1 R289.2 R296.2 R297.2 R300.2 R301.2 R311.2 R314.2 R321.2 R328.2 R329.2 R330.2 R331.2 R332.2 R335.2 R336.2 R337.2 R340.1 R342.2 R349.2 R351.1 R353.2 R361.2 R362.1 R365.1 R366.1 R371.2 R380.2 R382.2 R383.2 R397.2 R404.2 R406.2 R407.2 R421.1 R438.1 R462.1 R480.1 R486.2 R487.2 R497.2 R498.2 R500.2 R501.2 R513.2 R520.2 R522.2 R523.2 TP4.1(TP) TP57.1(TP) U1.4(GND) U2.43(RES1) U2.47(RES0) U2.54(NC) U2.61(GND) U3.2(1DIR) U3.3(2DIR) U3.8(GND1) U3.9(GND2) U4.2(1DIR) U4.3(2DIR) U4.8(GND1) U4.9(GND2) U5.8(GND1) U5.9(GND2) U6.4(GND#4) U6.10(GND#10) U6.15(GND#15) U6.21(GND#21) U6.28(GND#28) U6.34(GND#34) U6.39(GND#39) U6.45(GND#45) U7.4(GND#4) U7.10(GND#10) U7.15(GND#15) U7.21(GND#21) U7.28(GND#28) U7.34(GND#34) U7.39(GND#39) U7.45(GND#45) U8.49(GND) U9.1(GND) U10.8(GND#8) U10.19(GND#19) U10.38(GND#38) U10.49(GND#49) U11.8(GND#8) U11.19(GND#19) U11.38(GND#38) U11.49(GND#49) U12.8(GND#8) U12.19(GND#19) U12.38(GND#38) U12.49(GND#49) U13.2(GND) U14.11(GND1) U14.12(GND2) U14.13(GND3) U14.16(B6) U14.19(B3) U14.22(O\E\) U15.9(GND) U15.25(PAD) U16.4(V-) U17.8(GND) U17.15(O\E\) U18.4(V-) U19.2(AGNDAD2) U19.11(DGND2) U19.16(AGNDDA1) U19.33(AGNDDA2) U19.47(DGND1) U19.50(AGNDAD1) U19.65(EP) U20.4(V-) U21.4(GND) U22.4(V-) U23.4(V-) U24.4(V-) U25.4(GND) U26.4(V-) U27.4(V-) U28.4(V-) U29.4(V-) U30.4(VSS) U31.4(V-) U32.2(AGNDAD2) U32.11(DGND2) U32.16(AGNDDA1) U32.33(AGNDDA2) U32.47(DGND1) U32.50(AGNDAD1) U32.65(EP) U33.4(V-) U34.6(GND1) U34.14(GND2) U34.19(GND3) U35.4(GND) U36.1(GND) U37.1(GND) U38.2(GND) U39.3(GND) U40.2(GND) U40.15(EP) U41.16(DGND1) U41.17(PGND) U41.20(TGND1) U41.26(TGND2) U41.32(TGND3) U41.34(RESERVED) U41.48(DGND2) U41.64(DGND3) U41.65(EPAD) U42.5(GND#5) U42.10(GND#10) U43.9(GND) U43.25(PAD) U44.2(GND) U44.15(EP) U45.6(DGND) U45.23(AGND) U46.4(V-) U47.4(V-) U48.4(V-) U49.4(V-) U50.4(V-) U51.4(V-) U52.4(V-) U53.4(V-) U54.4(V-) U55.4(V-) U56.4(V-) U57.4(V-) U179.4(V-) U180.4(V-)
V3V3_OPTICAL: C46.1 L1.2 MOD1.1(VCC)
V5V0_HDMI1_CONN: C6.1 J4.18(5V) U34.13(5V_OUT)
VCC_1V8: C127.1 C128.1 C258.1 FL23.1 J2.114 J2.116 J2.118 R54.1 R68.1 R69.1 R339.1 TP7.1(TP) U9.2(VREF1)
VCC_3V3: C14.1 C27.1 C39.1 C40.1 C43.1 C44.1 C45.1 C48.1 C49.1 C50.1 C54.1 C70.1 C86.1 C109.1 C136.1 C162.1 C174.1 C176.1 C182.1 C213.1 C222.1 C224.1 C234.1 C236.1 C241.1 C244.2 C245.2 C246.2 C247.1 C248.2 C249.1 C250.2 C262.1 C263.1 C265.1 C266.1 C268.1 C269.1 C271.1 C273.1 FL2.1 FL4.2 FL6.2 FL15.1 FL20.2 FL21.2 FL22.2 FL24.2 FL25.1 L1.1 R6.2 R7.2 R8.2 R13.1 R15.2 R17.1 R20.1 R29.1 R30.2 R32.1 R56.1 R62.1 R64.1 R103.1 R110.1 R152.2 R171.1 R206.1 R208.1 R246.1 R248.1 R249.1 R251.1 R260.1 R264.1 R267.2 R298.1 R310.1 R322.2 R325.1 R333.1 R334.1 R338.2 R341.1 R343.1 R344.1 R345.1 R347.1 R348.1 R350.1 R352.2 R354.1 R356.2 R357.2 R358.1 R360.2 R363.2 R364.2 R367.1 R374.1 R376.1 R393.2 R394.2 R473.1 R485.2 R491.2 TP12.1(TP) U3.10(2B2) U3.13(1B1) U3.16(VCCB) U4.16(VCCB) U5.2(1DIR) U5.3(2DIR) U5.7(2A2) U5.16(VCCB) U6.1(1DIR) U6.7(VCCB#7) U6.18(VCCB#18) U6.24(2DIR) U7.1(1DIR) U7.7(VCCB#7) U7.18(VCCB#18) U7.24(2DIR) U7.29(2A6) U7.30(2A5) U8.30(VDDIO) U13.5(VCC) U14.1(VCCA) U14.23(VCCB1) U14.24(VCCB2) U15.21(VCCP) U15.23(VCCI) U17.16(VCC) U21.8(VCC) U25.8(VCC) U30.8(VCC) U34.24(VCCA) U37.2(VREF1) U39.5(VCC) U43.21(VCCP) U43.23(VCCI) U45.5(VDD)
VCC_5V0: C4.1 C61.1 C63.1 C77.1 C97.1 C131.1 C133.1 C137.1 C138.1 C167.1 C195.1 C220.1 C261.1 C274.1 C275.1 FL1.1 FL7.2 FL8.1 FL9.1 FL10.2 FL11.1 FL12.1 J2.78 J2.80 J2.82 R319.1 R320.1 R327.2 TP5.1(TP) U10.17(VCC) U11.17(VCC) U12.17(VCC) U34.11(VCC5V)
VCC_12V: C110.1 C112.1 C239.1 C240.1 C260.1 C264.1 C346.1 C348.2 J1.2 J1.4 J1.6 J17.49 J17.50 J17.51 J17.52 J17.53 J17.54 TP6.1(TP) U40.8(VS#8) U40.9(VS#9) U40.10(VS#10) U44.8(VS#8) U44.9(VS#9) U44.10(VS#10)
VCC_12V_CON: C257.1 C259.2 D4.1(CATHODE) J7.2 U44.5(OUT1) U44.6(OUT2) U44.7(OUT3)
VCC_12V_FPD: C223.1 C230.2 D3.1(CATHODE) J5.3 U40.5(OUT1) U40.6(OUT2) U40.7(OUT3)
VCC_CAM_3V3: C19.1 C22.1 C218.1 C221.1 FL15.2 J6.1 J6.2 J6.3
VCC_CAM_5V0: C2.1 C3.1 C5.1 C7.1 C10.1 C210.1 C211.1 C212.1 FL1.2 J3.19 J3.21 J6.4 J6.5 U1.2(IN) U1.3(EN2)
VCC_CAM_IO: C1.1 C15.1 C214.1 C225.1 C226.1 C227.1 C228.1 C231.1 C232.1 C233.1 FL14.1 R1.2 R2.2 R3.2 R11.2 R313.1 R316.1 R317.1 U3.1(VCCA) U4.1(VCCA) U5.1(VCCA) U6.31(VCCA#31) U6.42(VCCA#42) U7.31(VCCA#31) U7.42(VCCA#42) U35.8(VCC) U36.2(VREF1)
VCC_CAM_OSC: C215.1 C216.1 FL14.2 R326.1 U38.4(VDD)
VCC_DIR: C270.1 C272.1 FL25.2 U45.24(VCC)
VCCAD1_5V0: C164.1 C165.1 C166.1 C178.1 C179.1 FL11.2 TP162.1(TP) U32.3(VCCAD2) U32.49(VCCAD1)
VCCAD2_5V0: C93.1 C94.1 C95.1 C101.1 C102.1 FL9.2 TP165.1(TP) U19.3(VCCAD2) U19.49(VCCAD1)
VCCDA1_5V0: C188.1 C190.1 C191.1 C192.1 C194.1 FL12.2 TP161.1(TP) U32.14(VCCDA1) U32.34(VCCDA2)
VCCDA2_5V0: C79.1 C80.1 C82.1 C83.1 C84.1 FL8.2 TP164.1(TP) U19.14(VCCDA1) U19.34(VCCDA2)
VCCP_IN: C99.1 C107.1 C116.1 C126.1 C130.1 C132.1 C141.1 C144.1 C149.1 C155.1 C314.1 C320.1 C325.1 C328.1 C334.1 C344.1 C352.1 C357.1 C765.1 C766.1 FL10.1 U20.8(V+) U22.8(V+) U23.8(V+) U24.8(V+) U26.8(V+) U27.8(V+) U28.8(V+) U29.8(V+) U48.8(V+) U49.8(V+) U50.8(V+) U51.8(V+) U52.8(V+) U53.8(V+) U54.8(V+) U55.8(V+) U179.8(V+) U180.8(V+)
VCCP_OUT: C58.1 C60.1 C62.1 C78.1 C85.1 C175.1 C201.1 C203.1 C285.1 C299.1 C365.1 C379.1 FL7.1 R105.1 R127.1 R139.1 R153.1 R250.1 R268.1 R286.1 R299.1 R368.1 R381.1 R392.1 R405.1 R482.1 R499.1 R510.1 R521.1 U16.8(V+) U18.8(V+) U31.8(V+) U33.8(V+) U46.8(V+) U47.8(V+) U56.8(V+) U57.8(V+)
VDD33_FPD: C41.1 FL6.1 U8.22(VDD33)
VDD33_UB926: C11.1 C12.1 C13.1 FL2.2 TP167.1(TP) U2.29(VDD33_B) U2.48(VDD33_A)
VDD_3V3_CODEC1: C180.1 C181.1 C369.1 R267.1 R271.2 R277.2 TP169.1(TP) U32.12(VDD2) U32.46(VDD1)
VDD_3V3_CODEC2: C87.1 C298.1 C303.1 R152.1 R159.2 R167.2 TP170.1(TP) U19.12(VDD2) U19.46(VDD1)
VDD_CDCE: C253.1 C255.1 FL23.2 U42.3(VDD)
VDDIO_UB926: C8.1 C9.1 C20.1 C25.1 FL4.1 TP168.1(TP) U2.13(VDDIO#13) U2.24(VDDIO#24) U2.38(VDDIO#38)
VDDOUT_CDCE: C252.1 C254.1 FL24.1 U42.6(VDDOUT#6) U42.7(VDDOUT#7)
VINOUT_MUX_SEL0: J2.32 R362.2 TP125.1(TP) U10.1(S0) U11.1(S0) U12.1(S0)
VINOUT_MUX_SEL1: J2.34 R356.1 TP126.1(TP) U10.56(S1) U11.56(S1) U12.56(S1)
VINOUT_MUX_SEL2: R348.2 U10.55(S2) U11.55(S2) U12.55(S2)
AIN1_N: C146.2 R219.2 R220.2 R224.2 TP59.1(TP) U32.51(VIN1-)
AIN1_P: C146.1 R231.2 R234.2 TP58.1(TP) U32.52(VIN1+)
AIN2_N: C160.2 R236.2 R238.2 R242.2 TP61.1(TP) U32.53(VIN2-)
AIN2_P: C160.1 R256.2 R257.2 TP60.1(TP) U32.54(VIN2+)
AIN3_N: C355.2 R469.2 R471.2 R477.2 U32.55(VIN3-)
AIN3_P: C355.1 R489.2 R490.2 U32.56(VIN3+)
AIN4_N: C340.2 R453.2 R454.2 R459.2 U32.57(VIN4-)
AIN4_P: C340.1 R466.2 R468.2 U32.58(VIN4+)
AIN5_N: C329.1 R445.2 R447.2 R448.2 U32.61(VIN5-)
AIN5_P: C329.2 R441.2 R442.2 U32.62(VIN5+)
AIN6_N: C140.1 R211.2 R212.2 R217.2 U32.63(VIN6-)
AIN6_P: C140.2 R221.2 R222.2 U32.64(VIN6+)
AOUT1_A: C376.1 R511.2 R512.1 R517.2 R519.2
AOUT1_B: C376.2 R515.1 R516.2 R517.1 R518.2
AOUT1_C: C374.1 R511.1 U57.2(-INA)
AOUT1_D: C377.1 R518.1 U57.3(+INA)
AOUT1_E: C377.2 R510.2 R513.1 R515.2
AOUT1_N: C378.2 U32.32(VOUT1-)
AOUT1_O: C374.2 R512.2 R514.1 U57.1(OUTA)
AOUT1_P: C375.2 U32.31(VOUT1+)
AOUT1N: C378.1 R519.1
AOUT1P: C375.1 R516.1
AOUT2_A: C383.1 R527.1 R529.2 R530.1 R531.2
AOUT2_B: C383.2 R524.1 R525.2 R527.2 R528.2
AOUT2_C: C381.1 R529.1 U57.6(-INB)
AOUT2_D: C384.1 R528.1 U57.5(+INB)
AOUT2_E: C384.2 R521.2 R523.1 R524.2
AOUT2_N: C385.2 U32.30(VOUT2-)
AOUT2_O: C381.2 R526.1 R530.2 U57.7(OUTB)
AOUT2_P: C382.2 U32.29(VOUT2+)
AOUT2N: C385.1 R531.1
AOUT2P: C382.1 R525.1
AOUT3_A: C208.1 R306.1 R307.1 R308.2 R309.2
AOUT3_B: C208.2 R302.1 R303.2 R305.2 R306.2
AOUT3_C: C205.1 R308.1 U33.2(-INA)
AOUT3_D: C207.1 R305.1 U33.3(+INA)
AOUT3_E: C207.2 R299.2 R301.1 R302.2
AOUT3_N: C209.2 TP63.1(TP) U32.28(VOUT3-)
AOUT3_O: C205.2 R304.1 R307.2 U33.1(OUTA)
AOUT3_P: C206.2 TP62.1(TP) U32.27(VOUT3+)
AOUT3N: C209.1 R309.1
AOUT3P: C206.1 R303.1
AOUT4_A: C200.1 R287.1 R288.2 R294.1 R295.2
AOUT4_B: C200.2 R291.1 R292.2 R293.2 R294.2
